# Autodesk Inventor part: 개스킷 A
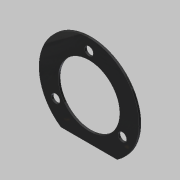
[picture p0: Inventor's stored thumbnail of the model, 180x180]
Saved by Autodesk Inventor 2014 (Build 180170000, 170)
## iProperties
Created: 2020-04
Part Number: 개스킷 A
Material: 고무
Document SubType Name: Modeling
Designer: mduedu
Density: 1 g/cm^3
Appearance: 고무 - 검은색 - 버전 1.1
Author: mduedu
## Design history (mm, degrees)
sketch "스케치1"
  geometry: C1 r 26 at (0, 0); 1 further point
  constraints: 1 centre point, 1 coincident
  dimensions: "d0" = 52 diameter of C1
extrude "돌출1" new body sketch "스케치1" distance "d1" = 1; taper "d2" = 0 deg
sketch "스케치2"
  geometry: L1 (-14.62, -21.5)-(14.62, -21.5); A1 r 26 centre (0, 0) between (-14.62, -21.5) and (14.62, -21.5) reference; 1 further point
  constraints: 2 end point, 2 point on circle, 1 horizontal
  dimensions: "d3" = 21.5 distance from line of L1 point (0, 0)
extrude "돌출2" cut sketch "스케치2" stored distance "d4" = 1; taper "d5" = 0 deg
sketch "스케치3" dims "d6" = 40
  geometry: 3 further points
  constraints: 2 vertical alignment, 1 coincident, 2 other
hole "구멍1" sketch "스케치3" at (0, 20) diameter "d7" = 4.5; stored, may be unused: countersink angle "d11" = 90 deg, drill point angle "d13" = 118 deg; dims "d8" = 6, "d9" = 4, "d10" = 2, "d12" = 8
sketch "스케치4"
  geometry: C1 r 16 at (0, 0); 1 further point
  constraints: 1 centre point, 1 coincident
  dimensions: "d17" = 32 diameter of C1
extrude "돌출3" cut sketch "스케치4" stored distance "d18" = 1; taper "d19" = 0 deg
node "솔리드1"
pattern_circular "원형 패턴1" dims angle "d15" = 360 deg
node "투영된 루프1"
